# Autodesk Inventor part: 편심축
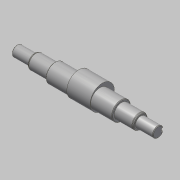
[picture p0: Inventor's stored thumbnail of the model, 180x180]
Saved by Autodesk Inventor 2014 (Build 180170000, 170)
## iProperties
Created: 2015-10
Part Number: 편심축
Document SubType Name: Modeling
Designer: mdu
Density: 1 g/cm^3
Material: 강철, 연강
Mass: 168.947 g
Surface Area: 248.524 cm^2
Volume: 168.947 cm^3
Appearance: 강철
Author: mdu
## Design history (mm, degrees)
sketch "스케치1"
  geometry: L1 (-20.5, -41.331)-(-20.5, 32.669) reference; L2 (7.5, -30.031)-(7.5, 21.369) reference; L3 (135.5, -30.331)-(135.5, 21.669) reference; L4 (121.5, 21.369)-(121.5, -30.031) reference; L5 (184.5, -4.331)-(-57.5, -4.331); L6 (184.5, -4.331)-(184.5, 4.669); L7 (154.5, 8.169)-(121.5, 8.169); L8 (121.5, 8.169)-(121.5, 11.669); L9 (121.5, 11.669)-(7.5, 11.669); L10 (7.5, 11.669)-(7.5, 8.169); L11 (7.5, 8.169)-(-27.5, 8.169); L12 (-27.5, 8.169)-(-27.5, 4.669); L13 (-27.5, 4.669)-(-57.5, 4.669); L14 (-57.5, 4.669)-(-57.5, -4.331); L15 (154.5, 8.169)-(154.5, 4.669); L16 (154.5, 4.669)-(184.5, 4.669); C1 r 32.5 at (64.5, -4.331) reference; 1 further point
  constraints: 24 end point, 8 perpendicular, 5 point on line, 3 parallel, 2 collinear
  dimensions: "d1" = 25 diameter of L11 L5; "d2" = 32 diameter of L9 L5; "d3" = 18 diameter of L13 L5; "d4" = 35 distance of L10.end L11.end; "d5" = 30 distance of L12.end L13.end; "d15" = 33 distance of L7.start L7.end; "d26" = 30 distance of L15.end L6.end
revolve "회전1" sketch "스케치1" stored, may be unused: angle "d6" = 90 deg
node "작업 평면1"
sketch "스케치2"
  geometry: C1 r 16 at (0, 0) reference; C2 r 20.75 at (0, 4)
  constraints: 1 centre point, 1 vertical alignment
  dimensions: "d34" = 4 distance of C2.centre C1.centre; "d35" = 41.5 diameter of C2
extrude "돌출1" join sketch "스케치2" stored distance "d9" = 40; taper "d10" = 0 deg
chamfer "모따기1" distance "d11" = 1; stored, may be unused: second distance "d12" = 2, angle "d13" = 45 deg
node "작업 평면2"
sketch "스케치3"
  geometry: L1 (-15, -8)-(-15, 8) reference; L2 (-15, 3)-(0, 3); L3 (0, -3)-(-15, -3); A1 r 3 centre (0, 0) between (0, -3) and (0, 3); 2 further points
  constraints: 4 end point, 2 perpendicular, 2 point on circle, 2 point on line, 2 tangent, 1 centre point, 1 horizontal alignment, 1 midpoint
  dimensions: "d16" = 18 dimension on A1 L1; "d17" = 6 distance between parallel lines of L3 L2
extrude "돌출2" cut sketch "스케치3" distance "d18" = 3.5; taper "d19" = 0 deg
node "작업 평면3"
chamfer "모따기2" distance "d36" = 2.2; stored, may be unused: second distance "d37" = 2, angle "d38" = 30 deg
chamfer "모따기3" distance "d39" = 2.2; stored, may be unused: second distance "d40" = 2, angle "d41" = 30 deg
fillet "모깎기1" dims "d42" = 1, "d43" = 2
fillet "모깎기2" dims "d44" = 1, "d45" = 2
node "솔리드1"
mirror "대칭1"
node "참조1"
node "참조2"
node "참조3"
node "참조4"
node "참조5"
other parameters: "d30" = 35
